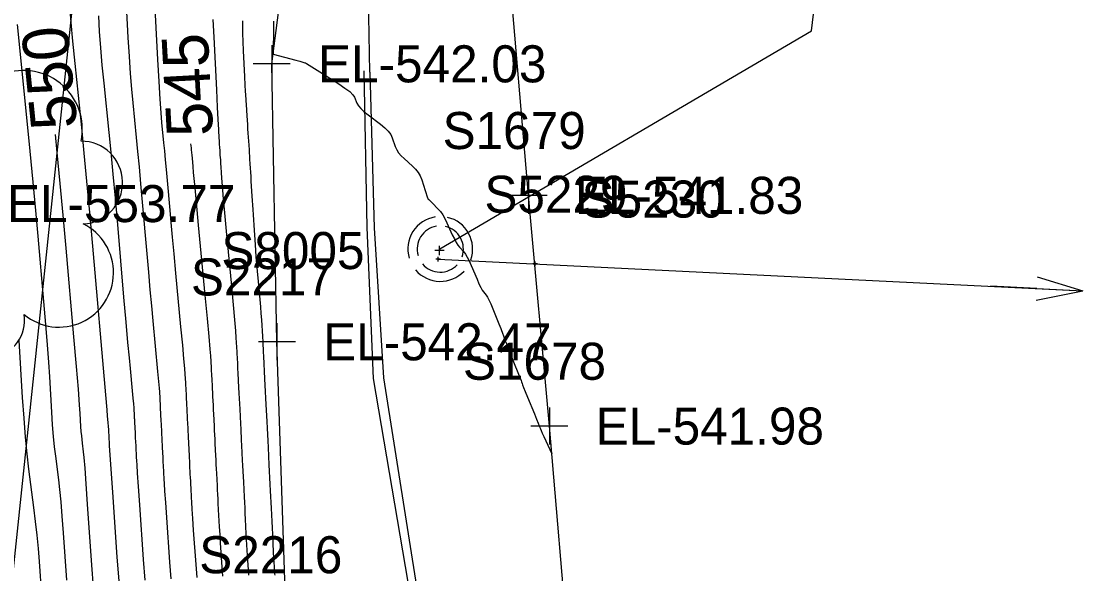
# Model space of a CAD drawing. Extents: x 1724534 to 1727318, y 657156 to 660047.
# Drawn here: x 1725501.3 to 1725616, y 658773.4 to 658833 of the extents above; entities that cross this region are included whole.
import ezdxf

# ---------------------------------------------------------------- set-up
doc = ezdxf.new("R2010")
doc.units = 0
for name, color, linetype in [('SURVEY - CONTOURS - Index with Text', 7, 'Continuous'), ('SURVEY - CONTOURS - Intermediate with optional Text', 7, 'Continuous'), ('SURVEY - DRAINAGE - Storm Sewer', 7, 'Continuous'), ('SURVEY - DRAINAGE - Storm Sewer - Points - Locators', 7, 'Continuous'), ('SURVEY - DRAINAGE - Storm Sewer - Points - Numbers', 7, 'Continuous'), ('SURVEY - DRAINAGE - Storm Sewer Text', 7, 'Continuous'), ('SURVEY - DTM - Breaklines', 7, 'Continuous'), ('SURVEY - DTM - Breaklines - Points - Elevations', 7, 'Continuous'), ('SURVEY - DTM - Breaklines - Points - Locators', 7, 'Continuous'), ('SURVEY - DTM - Breaklines - Points - Numbers', 7, 'Continuous'), ('SURVEY - MISCELLANEOUS - Bottom of MH and CB', 7, 'Continuous'), ('SURVEY - MISCELLANEOUS - Bottom of MH and CB - Points - Numbers', 7, 'Continuous'), ('SURVEY - TRANSPORTATION - Features', 7, 'Continuous'), ('SURVEY - TRANSPORTATION - Features - Points - Elevations', 7, 'Continuous'), ('SURVEY - TRANSPORTATION - Features - Points - Locators', 7, 'Continuous'), ('SURVEY - TRANSPORTATION - Features - Points - Numbers', 7, 'Continuous'), ('SURVEY - UTILITIES - Electric (Underground) with Text', 7, 'Continuous'), ('SURVEY - UTILITIES - Fiber Optic Cable (Underground) with Text', 7, 'Continuous'), ('SURVEY - UTILITIES - Overhead Wire Crossings', 7, 'Continuous'), ('SURVEY - VEGETATION - Features - Points - Elevations', 7, 'Continuous'), ('SURVEY - VEGETATION - Features with Text', 7, 'Continuous')]:
    doc.layers.add(name, color=color, linetype=linetype)

msp = doc.modelspace()

# ---------------------------------------------------------------- linework, layer by layer
at = {"layer": 'SURVEY - CONTOURS - Index with Text'}
for points in [[(1725504.94, 658820.81), (1725505.13, 658818.87), (1725505.45, 658815.53), (1725505.77, 658812.1), (1725506.08, 658808.55), (1725506.92, 658798.96), (1725507.2, 658795.75), (1725507.41, 658793.3), (1725507.54, 658791.62), (1725507.61, 658790.7), (1725507.69, 658789.27), (1725507.73, 658788.76), (1725507.77, 658788.29), (1725507.81, 658787.87), (1725507.85, 658787.49), (1725507.97, 658786.54), (1725508.04, 658785.92), (1725508.13, 658784.77), (1725508.25, 658783.1), (1725508.41, 658780.89), (1725508.86, 658774.32), (1725509.04, 658771.93)], [(1725519.58, 658819.82), (1725519.63, 658819.38), (1725519.65, 658819.14), (1725519.68, 658818.86), (1725519.71, 658818.57), (1725519.74, 658818.24), (1725519.81, 658817.34), (1725519.87, 658816.69), (1725519.99, 658815.41), (1725520.17, 658813.52), (1725520.41, 658811.01), (1725521.12, 658803.47), (1725521.36, 658800.94), (1725521.54, 658799), (1725521.66, 658797.65), (1725521.71, 658796.9), (1725521.79, 658795.67), (1725521.81, 658795.26), (1725521.83, 658794.98), (1725521.84, 658794.8), (1725521.84, 658794.74), (1725521.84, 658794.74), (1725521.85, 658794.68), (1725521.86, 658794.5), (1725521.87, 658794.21), (1725521.89, 658793.79), (1725521.95, 658792.53), (1725521.98, 658792.06), (1725522, 658791.58), (1725522.03, 658791.1), (1725522.05, 658790.63), (1725522.11, 658789.35), (1725522.14, 658788.87), (1725522.16, 658788.4), (1725522.19, 658787.92), (1725522.21, 658787.43), (1725522.27, 658786.15), (1725522.3, 658785.67), (1725522.32, 658785.18), (1725522.35, 658784.7), (1725522.37, 658784.21), (1725522.44, 658782.92), (1725522.46, 658782.43), (1725522.48, 658781.95), (1725522.51, 658781.46), (1725522.53, 658780.97), (1725522.6, 658779.66), (1725522.63, 658779.11), (1725522.67, 658778.44), (1725522.72, 658777.64), (1725522.78, 658776.72), (1725522.96, 658774.1), (1725523.04, 658773.11)]]:
    msp.add_lwpolyline(points, dxfattribs=at)
at = {"layer": 'SURVEY - CONTOURS - Intermediate with optional Text'}
for points in [[(1725512.51, 658836.9), (1725512.8, 658831.27), (1725512.92, 658829.24), (1725513.04, 658827.39), (1725513.18, 658825.72), (1725513.32, 658824.22), (1725513.7, 658820.47), (1725513.85, 658818.97), (1725514.01, 658817.31), (1725514.17, 658815.49), (1725514.35, 658813.49), (1725514.83, 658807.94), (1725515.01, 658805.93), (1725515.18, 658804.05), (1725515.34, 658802.31), (1725515.49, 658800.7), (1725516.01, 658795.21), (1725516.11, 658794.15), (1725516.17, 658793.42), (1725516.2, 658793.01), (1725516.24, 658792.33), (1725516.25, 658792.11), (1725516.26, 658791.96), (1725516.27, 658791.86), (1725516.27, 658791.83), (1725516.27, 658791.83), (1725516.27, 658791.8), (1725516.28, 658791.7), (1725516.29, 658791.54), (1725516.3, 658791.31), (1725516.33, 658790.62), (1725516.37, 658789.85), (1725516.38, 658789.59), (1725516.43, 658788.63), (1725516.44, 658788.37), (1725516.46, 658788.11), (1725516.47, 658787.84), (1725516.51, 658787.14), (1725516.52, 658786.88), (1725516.53, 658786.62), (1725516.55, 658786.35), (1725516.56, 658786.09), (1725516.59, 658785.38), (1725516.61, 658785.12), (1725516.65, 658784.32), (1725516.68, 658783.6), (1725516.71, 658783.14), (1725516.77, 658782.3), (1725516.85, 658781.07), (1725516.96, 658779.46), (1725517.29, 658774.65), (1725517.43, 658772.84)], [(1725515.63, 658835.8), (1725516, 658828.91), (1725516.13, 658826.55), (1725516.25, 658824.63), (1725516.35, 658823.15), (1725516.44, 658822.11), (1725516.66, 658819.92), (1725516.75, 658819.05), (1725516.84, 658818.09), (1725516.94, 658817.03), (1725517.04, 658815.86), (1725517.32, 658812.64), (1725517.44, 658811.31), (1725517.59, 658809.73), (1725517.75, 658807.91), (1725517.95, 658805.85), (1725518.5, 658800.03), (1725518.69, 658798.08), (1725518.82, 658796.58), (1725518.91, 658795.54), (1725518.96, 658794.95), (1725519.01, 658794), (1725519.03, 658793.69), (1725519.05, 658793.47), (1725519.05, 658793.33), (1725519.06, 658793.29), (1725519.06, 658793.29), (1725519.06, 658793.24), (1725519.07, 658793.1), (1725519.08, 658792.87), (1725519.09, 658792.55), (1725519.14, 658791.58), (1725519.16, 658791.21), (1725519.18, 658790.84), (1725519.2, 658790.47), (1725519.22, 658790.11), (1725519.27, 658789.12), (1725519.28, 658788.75), (1725519.3, 658788.38), (1725519.32, 658788.01), (1725519.34, 658787.64), (1725519.39, 658786.65), (1725519.41, 658786.27), (1725519.43, 658785.9), (1725519.45, 658785.53), (1725519.46, 658785.15), (1725519.51, 658784.15), (1725519.53, 658783.77), (1725519.55, 658783.4), (1725519.57, 658783.02), (1725519.59, 658782.64), (1725519.64, 658781.63), (1725519.67, 658781.13), (1725519.72, 658780.37), (1725519.78, 658779.36), (1725519.87, 658778.09), (1725520.13, 658774.37), (1725520.24, 658772.98)], [(1725506.5, 658834.63), (1725506.64, 658832.92), (1725506.83, 658830.87), (1725507.07, 658828.46), (1725507.77, 658821.55), (1725508.05, 658818.81), (1725508.34, 658815.76), (1725508.64, 658812.4), (1725508.97, 658808.74), (1725510.37, 658792.69), (1725510.51, 658791.1), (1725510.57, 658790.4), (1725510.63, 658789.71), (1725510.67, 658789.3), (1725510.68, 658789.18), (1725510.69, 658789.11), (1725510.69, 658789), (1725510.7, 658788.96), (1725510.7, 658788.92), (1725510.7, 658788.92), (1725510.7, 658788.91), (1725510.7, 658788.9), (1725510.71, 658788.72), (1725510.71, 658788.67), (1725510.71, 658788.63), (1725510.72, 658788.59), (1725510.73, 658788.38), (1725510.73, 658788.34), (1725510.73, 658788.3), (1725510.73, 658788.25), (1725510.74, 658788.05), (1725510.74, 658788), (1725510.75, 658787.96), (1725510.75, 658787.84), (1725510.76, 658787.71), (1725510.76, 658787.67), (1725510.77, 658787.55), (1725510.79, 658787.18), (1725511.13, 658782.2), (1725511.62, 658775.19), (1725511.82, 658772.61)], [(1725509.61, 658833.62), (1725509.71, 658831.93), (1725509.84, 658830.16), (1725510, 658828.29), (1725510.19, 658826.34), (1725510.74, 658821.01), (1725510.95, 658818.89), (1725511.17, 658816.54), (1725511.41, 658813.95), (1725511.66, 658811.11), (1725512.34, 658803.25), (1725512.58, 658800.55), (1725512.77, 658798.37), (1725512.92, 658796.7), (1725513.03, 658795.55), (1725513.26, 658793.15), (1725513.33, 658792.35), (1725513.39, 658791.73), (1725513.43, 658791.3), (1725513.44, 658791.06), (1725513.47, 658790.67), (1725513.48, 658790.54), (1725513.48, 658790.45), (1725513.48, 658790.39), (1725513.48, 658790.37), (1725513.48, 658790.37), (1725513.49, 658790.35), (1725513.49, 658790.3), (1725513.49, 658790.2), (1725513.5, 658790.07), (1725513.52, 658789.67), (1725513.53, 658789.52), (1725513.54, 658789.37), (1725513.54, 658789.22), (1725513.55, 658789.06), (1725513.57, 658788.66), (1725513.58, 658788.51), (1725513.59, 658788.35), (1725513.59, 658788.2), (1725513.6, 658788.05), (1725513.62, 658787.64), (1725513.63, 658787.49), (1725513.64, 658787.33), (1725513.64, 658787.18), (1725513.65, 658787.02), (1725513.67, 658786.61), (1725513.68, 658786.46), (1725513.69, 658786.3), (1725513.7, 658786.15), (1725513.7, 658785.99), (1725513.73, 658785.58), (1725513.75, 658785.16), (1725513.81, 658784.23), (1725513.91, 658782.79), (1725514.05, 658780.83), (1725514.45, 658774.92), (1725514.63, 658772.7)], [(1725500.82, 658832.69), (1725501.84, 658822.64), (1725502.21, 658819.02), (1725502.54, 658815.67), (1725502.82, 658812.61), (1725503.07, 658809.82), (1725503.69, 658802.78), (1725503.9, 658800.28), (1725504.08, 658798.1), (1725504.22, 658796.22), (1725504.32, 658794.64), (1725504.54, 658790.84), (1725504.63, 658789.47), (1725504.73, 658788.22), (1725504.84, 658787.09), (1725504.96, 658786.08), (1725505.29, 658783.54), (1725505.41, 658782.47), (1725505.54, 658781.16), (1725505.67, 658779.6), (1725505.8, 658777.8), (1725506.15, 658772.68)], [(1725521.97, 658833.23), (1725522.07, 658831.32), (1725522.36, 658825.63), (1725522.45, 658823.77), (1725522.52, 658822.43), (1725522.58, 658821.36), (1725522.58, 658821.36), (1725522.58, 658821.34), (1725522.58, 658821.27), (1725522.59, 658821.17), (1725522.63, 658820.55), (1725522.64, 658820.38), (1725522.65, 658820.2), (1725522.66, 658820.02), (1725522.67, 658819.84), (1725522.71, 658819.35), (1725522.72, 658819.16), (1725522.74, 658818.78), (1725522.75, 658818.59), (1725522.79, 658818.07), (1725522.81, 658817.68), (1725522.84, 658817.27), (1725522.87, 658816.72), (1725522.89, 658816.51), (1725522.9, 658816.29), (1725522.92, 658816.08), (1725522.97, 658815.27), (1725523.01, 658814.8), (1725523.09, 658813.83), (1725523.23, 658812.35), (1725523.42, 658810.37), (1725523.98, 658804.43), (1725524.17, 658802.41), (1725524.32, 658800.81), (1725524.42, 658799.62), (1725524.47, 658798.84), (1725524.56, 658797.33), (1725524.61, 658796.49), (1725524.63, 658796.27), (1725524.63, 658796.13), (1725524.66, 658795.54), (1725524.69, 658795.03), (1725524.77, 658793.48), (1725524.79, 658792.9), (1725524.82, 658792.32), (1725524.85, 658791.73), (1725524.88, 658791.15), (1725524.96, 658789.58), (1725524.99, 658789), (1725525.05, 658787.82), (1725525.08, 658787.23), (1725525.16, 658785.65), (1725525.19, 658785.06), (1725525.22, 658784.47), (1725525.28, 658783.28), (1725525.36, 658781.69), (1725525.39, 658781.09), (1725525.42, 658780.49), (1725525.45, 658779.89), (1725525.48, 658779.29), (1725525.56, 658777.69), (1725525.59, 658777.09), (1725525.62, 658776.5), (1725525.66, 658775.92), (1725525.69, 658775.35), (1725525.8, 658773.82), (1725525.85, 658773.25)], [(1725525.18, 658833.09), (1725525.18, 658832.47), (1725525.19, 658831.72), (1725525.22, 658830.85), (1725525.27, 658829.86), (1725525.41, 658827.06), (1725525.45, 658826.15), (1725525.49, 658825.49), (1725525.51, 658825.1), (1725525.52, 658824.96), (1725525.52, 658824.96), (1725525.52, 658824.9), (1725525.53, 658824.73), (1725525.55, 658824.44), (1725525.57, 658824.04), (1725525.65, 658822.82), (1725525.68, 658822.36), (1725525.71, 658821.89), (1725525.74, 658821.42), (1725525.77, 658820.94), (1725525.86, 658819.65), (1725525.89, 658819.16), (1725525.95, 658818.16), (1725525.98, 658817.65), (1725526.07, 658816.28), (1725526.1, 658815.76), (1725526.14, 658815.23), (1725526.17, 658814.7), (1725526.21, 658814.16), (1725526.3, 658812.7), (1725526.34, 658812.15), (1725526.37, 658811.59), (1725526.41, 658811.02), (1725526.54, 658808.89), (1725526.59, 658808.27), (1725526.64, 658807.59), (1725526.7, 658806.85), (1725526.78, 658806.04), (1725526.99, 658803.81), (1725527.06, 658802.99), (1725527.13, 658802.21), (1725527.18, 658801.48), (1725527.23, 658800.79), (1725527.34, 658799), (1725527.37, 658798.41), (1725527.4, 658797.99), (1725527.41, 658797.74), (1725527.42, 658797.66), (1725527.42, 658797.66), (1725527.42, 658797.57), (1725527.43, 658797.31), (1725527.45, 658796.88), (1725527.58, 658794.44), (1725527.61, 658793.75), (1725527.65, 658793.06), (1725527.68, 658792.36), (1725527.72, 658791.67), (1725527.81, 658789.82), (1725527.84, 658789.12), (1725527.88, 658788.42), (1725527.91, 658787.72), (1725527.95, 658787.02), (1725528.04, 658785.16), (1725528.08, 658784.45), (1725528.11, 658783.75), (1725528.15, 658783.05), (1725528.18, 658782.34), (1725528.28, 658780.46), (1725528.31, 658779.75), (1725528.35, 658779.04), (1725528.38, 658778.33), (1725528.42, 658777.62), (1725528.51, 658775.72), (1725528.55, 658775.08), (1725528.57, 658774.57), (1725528.59, 658774.2), (1725528.61, 658773.97), (1725528.64, 658773.55), (1725528.65, 658773.39), (1725528.67, 658773.23)], [(1725528.55, 658833.06), (1725528.54, 658832.42), (1725528.49, 658829.5), (1725530.94, 658828.83), (1725531.39, 658828.71), (1725531.72, 658828.62), (1725531.92, 658828.56), (1725531.99, 658828.54), (1725532.1, 658828.47), (1725532.39, 658828.29), (1725533.54, 658827.57), (1725535.58, 658826.28), (1725536.26, 658825.83), (1725536.77, 658825.44), (1725537.12, 658825.1), (1725537.3, 658824.83), (1725537.56, 658824.18), (1725537.71, 658823.92), (1725537.96, 658823.63), (1725538.31, 658823.3), (1725538.77, 658822.93), (1725540.11, 658821.91), (1725540.57, 658821.53), (1725540.93, 658821.16), (1725541.2, 658820.8), (1725541.37, 658820.45), (1725541.7, 658819.52), (1725541.86, 658819.17), (1725542.06, 658818.84), (1725542.33, 658818.52), (1725542.65, 658818.21), (1725543.57, 658817.39), (1725543.89, 658817.07), (1725544.16, 658816.72), (1725544.38, 658816.33), (1725544.55, 658815.92), (1725544.92, 658814.77), (1725545.18, 658813.97), (1725545.2, 658813.92), (1725545.2, 658813.92), (1725545.23, 658813.88), (1725545.32, 658813.79), (1725545.48, 658813.64), (1725545.69, 658813.42), (1725546.35, 658812.76), (1725546.59, 658812.49), (1725546.83, 658812.15), (1725547.06, 658811.75), (1725547.28, 658811.29), (1725547.86, 658809.99), (1725548.08, 658809.54), (1725548.28, 658809.16), (1725548.47, 658808.86), (1725548.64, 658808.64), (1725549.1, 658808.14), (1725549.28, 658807.9), (1725549.47, 658807.58), (1725549.68, 658807.17), (1725549.91, 658806.66), (1725550.53, 658805.19), (1725550.74, 658804.7), (1725550.93, 658804.3), (1725551.09, 658804.01), (1725551.22, 658803.82), (1725551.53, 658803.46), (1725551.66, 658803.26), (1725551.82, 658802.95), (1725552.02, 658802.52), (1725552.24, 658801.98), (1725552.88, 658800.38), (1725553.09, 658799.85), (1725553.33, 658799.25), (1725553.36, 658799.17), (1725553.36, 658799.17), (1725553.37, 658799.16), (1725553.38, 658799.12), (1725553.4, 658799.06), (1725553.43, 658798.97), (1725553.52, 658798.7), (1725553.58, 658798.53), (1725553.7, 658798.23), (1725553.87, 658797.79), (1725555.02, 658794.95), (1725555.19, 658794.52), (1725555.3, 658794.24), (1725555.35, 658794.11), (1725555.4, 658793.94), (1725555.46, 658793.8), (1725555.57, 658793.51), (1725555.75, 658793.06), (1725556, 658792.46), (1725556.73, 658790.65), (1725556.97, 658790.06), (1725557.15, 658789.63), (1725557.25, 658789.37), (1725557.29, 658789.27), (1725557.32, 658789.2), (1725557.33, 658789.18), (1725557.36, 658789.09), (1725557.39, 658789.02), (1725557.47, 658788.85), (1725557.59, 658788.58), (1725557.75, 658788.22), (1725558.61, 658786.32)], [(1725501.03, 658798.58), (1725501.39, 658792.4), (1725501.54, 658790.18), (1725501.7, 658788.15), (1725501.88, 658786.32), (1725502.07, 658784.68), (1725502.61, 658780.55), (1725502.79, 658779.03), (1725502.95, 658777.54), (1725503.09, 658776.1), (1725503.2, 658774.71), (1725503.45, 658771.04)]]:
    msp.add_lwpolyline(points, dxfattribs=at)
at = {"layer": 'SURVEY - DRAINAGE - Storm Sewer'}
for p, q in [((1725546.33, 658807.36), (1725616, 658803.94)), ((1725611.07, 658805.43), (1725616, 658803.94)), ((1725611.02, 658804.19), (1725606.03, 658804.43)), ((1725610.96, 658802.94), (1725616, 658803.94)), ((1725611.02, 658804.19), (1725616, 658803.94)), ((1725611.02, 658804.19), (1725616, 658803.94))]:
    msp.add_line(p, q, dxfattribs=at)
for radius, start, end in [(3.5, 98.9594, 196.2542), (3.5, 340.5532, 76.9994), (2.5, 99.7619, 196.2001), (2.5, 340.5504, 77.0954), (3.5, 220.3962, 317.1893), (2.5, 220.3142, 317.1488)]:
    msp.add_arc((1725546.56, 658808.45), radius, start, end, dxfattribs=at)
at = {"layer": 'SURVEY - DRAINAGE - Storm Sewer - Points - Locators'}
for p, q in [((1725546.58, 658807.36), (1725546.08, 658807.36)), ((1725546.33, 658807.11), (1725546.33, 658807.61)), ((1725546.33, 658807.36), (1725546.33, 658807.36)), ((1725546.33, 658807.36), (1725546.33, 658807.36)), ((1725556.83, 658806.59), (1725556.83, 658807.09)), ((1725557.08, 658806.84), (1725556.58, 658806.84)), ((1725556.83, 658806.84), (1725556.83, 658806.84)), ((1725556.83, 658806.84), (1725556.83, 658806.84))]:
    msp.add_line(p, q, dxfattribs=at)
at = {"layer": 'SURVEY - DRAINAGE - Storm Sewer Text'}
msp.add_lwpolyline([(1725546.53, 658808.46), (1725586.68, 658832), (1725592.59, 658881.14)], dxfattribs=at)
at = {"layer": 'SURVEY - DTM - Breaklines'}
msp.add_lwpolyline([(1725533.45, 658738.58), (1725529.91, 658768.44), (1725528.9, 658798.43), (1725528.35, 658828.44), (1725532.27, 658858.68), (1725531.3, 658888.67), (1725527.69, 658918.53), (1725523.84, 658948.37), (1725524.63, 658981.77), (1725524.81, 658996.21), (1725524.72, 658997.15)], dxfattribs=at)
at = {"layer": 'SURVEY - DTM - Breaklines - Points - Locators'}
for p, q in [((1725528.35, 658830.44), (1725528.35, 658826.44)), ((1725530.35, 658828.44), (1725526.35, 658828.44)), ((1725528.9, 658800.43), (1725528.9, 658796.43)), ((1725530.9, 658798.43), (1725526.9, 658798.43))]:
    msp.add_line(p, q, dxfattribs=at)
at = {"layer": 'SURVEY - MISCELLANEOUS - Bottom of MH and CB'}
for p, q in [((1725546.98, 658808.28), (1725545.98, 658808.28)), ((1725546.48, 658807.78), (1725546.48, 658808.78)), ((1725546.48, 658808.28), (1725546.48, 658808.28)), ((1725546.48, 658808.28), (1725546.48, 658808.28))]:
    msp.add_line(p, q, dxfattribs=at)
at = {"layer": 'SURVEY - TRANSPORTATION - Features'}
msp.add_lwpolyline([(1725570.83, 658646.25), (1725568.8, 658661.12), (1725567.73, 658676.05), (1725566.05, 658695.42), (1725564.66, 658714.5), (1725562.73, 658739.43), (1725560.5, 658764.33), (1725558.35, 658789.33), (1725556.11, 658814.24), (1725553.97, 658839.15), (1725552.26, 658864.38), (1725550.91, 658889.35), (1725550.24, 658914.34), (1725548.73, 658939.31), (1725548.54, 658964.32)], dxfattribs=at)
at = {"layer": 'SURVEY - TRANSPORTATION - Features - Points - Locators'}
for p, q in [((1725556.11, 658816.24), (1725556.11, 658812.24)), ((1725558.11, 658814.24), (1725554.11, 658814.24)), ((1725558.35, 658791.33), (1725558.35, 658787.33)), ((1725560.35, 658789.33), (1725556.35, 658789.33))]:
    msp.add_line(p, q, dxfattribs=at)
at = {"layer": 'SURVEY - UTILITIES - Electric (Underground) with Text'}
msp.add_lwpolyline([(1725538.31, 658827.7), (1725538.61, 658810.76), (1725539.31, 658794.45), (1725544.8, 658762.34), (1725548.91, 658731.4), (1725555.84, 658694.73), (1725557.58, 658674.8)], dxfattribs=at)
at = {"layer": 'SURVEY - UTILITIES - Fiber Optic Cable (Underground) with Text'}
msp.add_line((1725538.95, 658827.55), (1725533.82, 659093.21), dxfattribs=at)
msp.add_lwpolyline([(1725538.95, 658827.55), (1725539.43, 658810.74), (1725540.41, 658794.55), (1725545.54, 658762.23), (1725549.45, 658731.33), (1725556.37, 658694.76), (1725557.94, 658674.86)], dxfattribs=at)
at = {"layer": 'SURVEY - UTILITIES - Overhead Wire Crossings'}
msp.add_line((1725512.62, 658889.98), (1725457.38, 658365.55), dxfattribs=at)
at = {"layer": 'SURVEY - VEGETATION - Features with Text'}
for centre, radius, start, end in [((1725501.54, 658821.39), 6.33, 348.1042, 114.9499), ((1725507.75, 658815.62), 4.47, 272.8171, 90.1363), ((1725505.36, 658805.89), 5.88, 230.1985, 63.6182), ((1725497.6, 658800.75), 4.04, 190.1778, 8.9234)]:
    msp.add_arc(centre, radius, start, end, dxfattribs=at)

# ---------------------------------------------------------------- texts
at = {"layer": 'SURVEY - CONTOURS - Index with Text'}
for s, rotation, p in [('550', 95.7591, (1725507.36, 658821.61)), ('545', 93.1119, (1725522.02, 658820.72))]:
    msp.add_text(s, height=5, rotation=rotation, dxfattribs=at).set_placement(p)
at = {"layer": 'SURVEY - DRAINAGE - Storm Sewer - Points - Numbers'}
for s, p in [('S5229', (1725551.33, 658812.36)), ('S5230', (1725561.83, 658811.84))]:
    msp.add_text(s, height=4, dxfattribs=at).set_placement(p)
at = {"layer": 'SURVEY - DTM - Breaklines - Points - Elevations'}
for s, p in [('EL-542.03', (1725533.35, 658826.44)), ('EL-542.47', (1725533.9, 658796.43))]:
    msp.add_text(s, height=4, dxfattribs=at).set_placement(p)
at = {"layer": 'SURVEY - DTM - Breaklines - Points - Numbers'}
for s, p in [('S2217', (1725519.61, 658803.43)), ('S2216', (1725520.51, 658773.44))]:
    msp.add_text(s, height=4, dxfattribs=at).set_placement(p)
at = {"layer": 'SURVEY - MISCELLANEOUS - Bottom of MH and CB - Points - Numbers'}
msp.add_text('S8005', height=4, dxfattribs=at).set_placement((1725522.9, 658806.28))
at = {"layer": 'SURVEY - TRANSPORTATION - Features - Points - Elevations'}
for s, p in [('EL-541.83', (1725561.11, 658812.24)), ('EL-541.98', (1725563.35, 658787.33))]:
    msp.add_text(s, height=4, dxfattribs=at).set_placement(p)
at = {"layer": 'SURVEY - TRANSPORTATION - Features - Points - Numbers'}
for s, p in [('S1679', (1725546.81, 658819.24)), ('S1678', (1725549.01, 658794.33))]:
    msp.add_text(s, height=4, dxfattribs=at).set_placement(p)
at = {"layer": 'SURVEY - VEGETATION - Features - Points - Elevations'}
msp.add_text('EL-553.77', height=4, dxfattribs=at).set_placement((1725499.73, 658811.35))

doc.saveas('drawing.dxf')
